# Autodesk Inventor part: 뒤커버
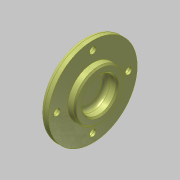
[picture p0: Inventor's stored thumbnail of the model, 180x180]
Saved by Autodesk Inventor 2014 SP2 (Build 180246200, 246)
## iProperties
Created: 2015-12
Part Number: 뒤커버
Document SubType Name: Modeling
Designer: mdu
Density: 2.71 g/cm^3
Material: 알루미늄 6061
Mass: 56.2007 g
Surface Area: 84.0408 cm^2
Volume: 20.7383 cm^3
Appearance: 알루미늄 - 평지
Author: mdu
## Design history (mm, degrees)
sketch "스케치1"
  geometry: L1 (-7, 0)-(7, 0); L2 (-7, 0)-(-7, 15.539); L3 (-7, 15.539)-(-4, 18.5); L4 (-4, 18.5)-(-4, 31); L5 (-4, 31)-(2, 31); L6 (2, 31)-(2, 17.5); L7 (2, 17.5)-(7, 17.5); L8 (7, 17.5)-(7, 0); 2 further points
  constraints: 16 end point, 4 parallel, 2 perpendicular, 1 coincident, 1 horizontal, 1 midpoint
  dimensions: "d0" = 14 distance of L1.start L1.end; "d1" = 62 diameter of L5 L1; "d2" = 35 diameter of L7 L1; "d3" = 37 diameter of L3.end L1; "d4" = 3 distance between parallel lines of L4 L2; "d5" = 6 distance of L4.end L5.end
revolve "회전1" sketch "스케치1" stored, may be unused: angle "d6" = 90 deg
sketch "스케치2" dims "d32" = 50
  geometry: 3 further points
  constraints: 2 vertical alignment, 1 coincident, 2 other
hole "구멍1" sketch "스케치2" at (0, 25) diameter "d8" = 4.5; stored, may be unused: countersink angle "d12" = 90 deg, drill point angle "d14" = 118 deg; dims "d9" = 6, "d10" = 8, "d11" = 4.4, "d13" = 8
hole "구멍2" diameter "d20" = 24; stored, may be unused: countersink angle "d24" = 90 deg, drill point angle "d26" = 0 deg; dims "d18" = 10, "d19" = 10, "d21" = 6, "d22" = 8, "d23" = 4.4, "d25" = 8
fillet "모깎기1" dims "d27" = 3
fillet "모깎기2" dims "d28" = 3
chamfer "모따기1" distance "d29" = 1; stored, may be unused: second distance "d30" = 2, angle "d31" = 45 deg
node "솔리드1"
pattern_circular "원형 패턴1" dims angle "d16" = 360 deg
